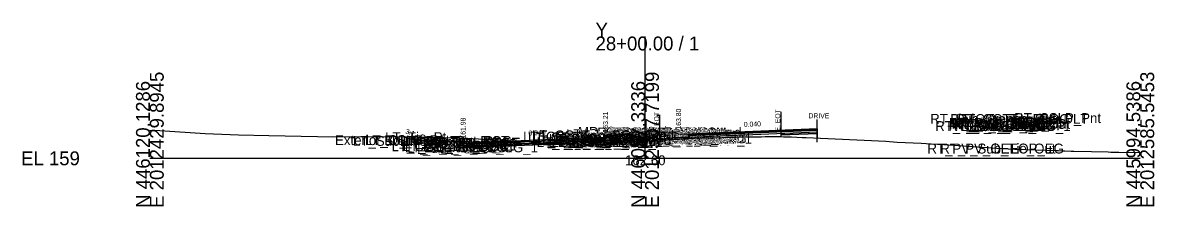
# Model space of a CAD drawing. Extents: x -26 to 3203, y -10 to 9532.
# Drawn here: x 1974.3 to 2202.8, y 1990.3 to 2027.4 of the extents above; entities that cross this region are included whole.
import ezdxf

# ---------------------------------------------------------------- set-up
doc = ezdxf.new("R2010")
doc.units = 0
for name, color, linetype in [('Default', 7, 'Continuous'), ('Exist CMT Pavement', 7, 'Continuous'), ('Exist Cross Section Cell', 7, 'Continuous'), ('Exist XS Center Line Elevation Label', 7, 'Continuous'), ('Exist XS Ground Line', 7, 'Continuous'), ('Prop CMT Conc Surface', 7, 'Continuous'), ('Prop CMT Concrete Structures', 7, 'Continuous'), ('Prop CMT Pvmt Course 1', 7, 'Continuous'), ('Prop CMT Pvmt Course 1 CG', 7, 'Continuous'), ('Prop CMT Pvmt Course 2', 7, 'Continuous'), ('Prop CMT Pvmt Course 2 Wedge', 7, 'Continuous'), ('Prop CMT Pvmt Course 3', 7, 'Continuous'), ('Prop CMT Pvmt Course 3 Wedge', 7, 'Continuous'), ('Prop CMT Pvmt Surface', 7, 'Continuous'), ('Prop CMT Shear Line', 7, 'Continuous'), ('Prop CMT Shear Line Text', 7, 'Continuous'), ('Prop CMT Slope Grass', 7, 'Continuous'), ('Prop CMT Subgrade Earthwork', 7, 'Continuous'), ('Prop XS Hydro Elevations', 7, 'Continuous'), ('Prop XS Label Text', 7, 'Continuous'), ('Prop XS SE Text', 7, 'Continuous'), ('Prop XS Side Slope Text', 7, 'Continuous'), ('Scratch_Level_0', 7, 'Continuous')]:
    doc.layers.add(name, color=color, linetype=linetype)

msp = doc.modelspace()

# ---------------------------------------------------------------- linework, layer by layer
at = {"layer": 'Exist CMT Pavement'}
msp.add_lwpolyline([(2102.94, 2003.8), (2103.42, 2003.84), (2104, 2003.86), (2105.57, 2003.91), (2106.47, 2003.95), (2107.66, 2004), (2108.25, 2004.02), (2108.72, 2004.03), (2111.56, 2004.1), (2111.97, 2004.11), (2113.68, 2004.16), (2115.52, 2004.23), (2116.81, 2004.25), (2118.35, 2004.29), (2119.47, 2004.31), (2120.62, 2004.34), (2121.54, 2004.35), (2122.41, 2004.35), (2123.51, 2004.36), (2124.23, 2004.37), (2124.81, 2004.38), (2126.83, 2004.38), (2127.38, 2004.37), (2127.38, 2004.37)], dxfattribs=at)
at = {"layer": 'Exist Cross Section Cell'}
for p, q in [((2100, 2000), (2100, 2024.57)), ((2000, 2000), (2100, 2000)), ((2100, 2000), (2200, 2000))]:
    msp.add_line(p, q, dxfattribs=at)
at = {"layer": 'Exist XS Ground Line'}
msp.add_lwpolyline([(2000, 2005.67), (2001.98, 2005.58), (2011.14, 2004.99), (2017.91, 2004.74), (2023.99, 2004.6), (2033.83, 2004.38), (2036.84, 2004.34), (2049.76, 2004.39), (2062.54, 2004.11), (2063.94, 2004.04), (2073.65, 2003.51), (2076.49, 2003.36), (2076.94, 2003.34), (2077.71, 2003.28), (2088.98, 2002.56), (2093.02, 2003.01), (2095.39, 2003.3), (2100, 2003.6), (2102.94, 2003.8), (2103.42, 2003.84), (2104, 2003.86), (2105.57, 2003.91), (2106.47, 2003.95), (2107.66, 2004), (2108.25, 2004.02), (2108.72, 2004.03), (2111.56, 2004.1), (2111.97, 2004.11), (2113.68, 2004.16), (2115.52, 2004.23), (2116.81, 2004.25), (2118.35, 2004.29), (2119.47, 2004.31), (2120.62, 2004.34), (2121.54, 2004.35), (2122.41, 2004.35), (2123.51, 2004.36), (2124.23, 2004.37), (2124.81, 2004.38), (2126.83, 2004.38), (2127.38, 2004.37), (2127.96, 2004.35), (2129.55, 2004.32), (2131.7, 2004.23), (2132.54, 2004.2), (2148.62, 2003.47), (2150.91, 2003.29), (2155.77, 2003.06), (2157.8, 2002.94), (2160.31, 2002.8), (2171.98, 2001.98), (2174.64, 2001.83), (2183.16, 2001.58), (2183.47, 2001.58), (2184.15, 2001.54), (2184.79, 2001.5), (2186.07, 2001.46), (2186.61, 2001.45), (2190.16, 2001.36), (2193.53, 2001.28), (2194.02, 2001.27), (2194.59, 2001.26), (2195.65, 2001.22), (2200, 2001.15)], dxfattribs=at)
at = {"layer": 'Prop CMT Conc Surface'}
for points in [[(2091.25, 2004.18), (2092, 2004.21), (2092, 2004.37), (2092.76, 2004.62)], [(2108.75, 2004.88), (2106.75, 2004.8), (2106.75, 2004.96), (2106, 2005.21)], [(2058.75, 2003.57), (2053.75, 2003.67)], [(2063.25, 2002.98), (2063.25, 2003.48), (2062.75, 2003.48)], [(2065.25, 2003.14), (2063.25, 2002.98)]]:
    msp.add_lwpolyline(points, dxfattribs=at)
at = {"layer": 'Prop CMT Concrete Structures'}
for points in [[(2091.25, 2004.18), (2092, 2004.21), (2092, 2004.37), (2092.76, 2004.62)], [(2092.76, 2004.62), (2092.76, 2003.65)], [(2108.75, 2004.88), (2106.75, 2004.8), (2106.75, 2004.96), (2106, 2005.21)], [(2106, 2005.21), (2106, 2004.18)], [(2106, 2004.18), (2108.75, 2004.29)], [(2108.75, 2004.29), (2108.75, 2004.88)], [(2053.75, 2003.33), (2053.75, 2003.67)], [(2053.75, 2003.67), (2058.75, 2003.57)], [(2058.75, 2003.23), (2053.75, 2003.33)], [(2058.75, 2003.57), (2058.75, 2003.23)], [(2065.25, 2003.14), (2063.25, 2002.98), (2063.25, 2003.48), (2062.75, 2003.48)], [(2062.75, 2003.48), (2062.75, 2002.45), (2065.25, 2002.55)], [(2065.25, 2002.55), (2065.25, 2003.14)], [(2091.25, 2003.59), (2091.25, 2004.18)], [(2092.76, 2003.65), (2091.25, 2003.59)]]:
    msp.add_lwpolyline(points, dxfattribs=at)
at = {"layer": 'Prop CMT Pvmt Course 1'}
for points in [[(2172.41, 2007.42), (2172.41, 2007.17)], [(2108.75, 2004.88), (2134.75, 2005.92)], [(2134.75, 2005.67), (2108.75, 2004.63)], [(2108.75, 2004.63), (2108.75, 2004.88)], [(2108.75, 2004.63), (2108.75, 2004.63)], [(2134.75, 2005.92), (2134.75, 2005.67)], [(2134.75, 2005.92), (2134.75, 2005.67)], [(2091.25, 2004.18), (2065.25, 2003.14)], [(2065.25, 2002.89), (2091.25, 2003.93)], [(2065.25, 2003.14), (2065.25, 2002.89)], [(2091.25, 2003.93), (2091.25, 2004.18)], [(2091.25, 2003.93), (2091.25, 2003.93), (2091.25, 2003.93)]]:
    msp.add_lwpolyline(points, dxfattribs=at)
at = {"layer": 'Prop CMT Pvmt Course 1 CG'}
for points in [[(2108.75, 2004.29), (2105.5, 2004.16), (2105.15, 2003.82)], [(2108.75, 2003.96), (2108.75, 2004.29)], [(2134.75, 2005), (2134.75, 2005.33)], [(2065.25, 2002.55), (2062.25, 2002.43), (2061.9, 2002.09)], [(2061.9, 2002.09), (2065.25, 2002.22)], [(2065.25, 2002.22), (2065.25, 2002.55)], [(2091.25, 2003.59), (2093.26, 2003.67), (2093.58, 2003.35)], [(2091.25, 2003.26), (2091.25, 2003.59)], [(2093.58, 2003.35), (2091.25, 2003.26)], [(2105.15, 2003.82), (2108.75, 2003.96)]]:
    msp.add_lwpolyline(points, dxfattribs=at)
at = {"layer": 'Prop CMT Pvmt Course 2'}
msp.add_lwpolyline([(2108.75, 2004.63), (2108.75, 2004.29), (2108.75, 2004.29)], close=True, dxfattribs=at)
for points in [[(2108.75, 2004.63), (2108.75, 2004.63)], [(2134.75, 2005.67), (2134.75, 2005.33)], [(2091.25, 2003.93), (2065.25, 2002.89)], [(2065.25, 2002.55), (2091.25, 2003.59)], [(2065.25, 2002.89), (2065.25, 2002.55)], [(2091.25, 2003.59), (2091.25, 2003.93)]]:
    msp.add_lwpolyline(points, dxfattribs=at)
at = {"layer": 'Prop CMT Pvmt Course 2 Wedge'}
msp.add_lwpolyline([(2108.75, 2004.63), (2134.75, 2005.67)], dxfattribs=at)
at = {"layer": 'Prop CMT Pvmt Course 3'}
for points in [[(2108.75, 2004.29), (2108.75, 2004.29), (2108.75, 2003.96), (2108.75, 2003.96)], [(2108.75, 2003.96), (2108.75, 2004.29)], [(2127.38, 2004.71), (2134.75, 2005)], [(2134.75, 2005.33), (2134.75, 2004.22)], [(2091.25, 2003.59), (2065.25, 2002.55)], [(2065.25, 2002.22), (2091.25, 2003.26)], [(2065.25, 2002.55), (2065.25, 2002.22)], [(2091.25, 2003.26), (2091.25, 2003.59)]]:
    msp.add_lwpolyline(points, dxfattribs=at)
at = {"layer": 'Prop CMT Pvmt Course 3 Wedge'}
msp.add_lwpolyline([(2108.75, 2004.29), (2134.75, 2005.33)], dxfattribs=at)
at = {"layer": 'Prop CMT Pvmt Surface'}
for points in [[(2134.75, 2005.92), (2108.75, 2004.88)], [(2091.25, 2004.18), (2065.25, 2003.14)]]:
    msp.add_lwpolyline(points, dxfattribs=at)
at = {"layer": 'Prop CMT Shear Line'}
msp.add_line((2134.75, 2003.28), (2134.75, 2007.86), dxfattribs=at)
at = {"layer": 'Prop CMT Slope Grass'}
for points in [[(2053.25, 2003.67), (2051.17, 2004.36)], [(2092.76, 2004.62), (2099.38, 2005.35)], [(2106, 2005.21), (2099.38, 2005.35)], [(2062.75, 2003.48), (2053.25, 2003.67)]]:
    msp.add_lwpolyline(points, dxfattribs=at)
at = {"layer": 'Prop CMT Subgrade Earthwork'}
for points in [[(2095.11, 2004.88), (2093.58, 2003.35)], [(2103.71, 2005.26), (2105.15, 2003.82)], [(2134.75, 2005), (2127.38, 2004.71)], [(2134.75, 2005.33), (2134.75, 2004.1)], [(2134.75, 2005), (2134.75, 2005)], [(2065.25, 2002.22), (2061.9, 2002.09), (2060.47, 2003.52)], [(2091.25, 2003.26), (2065.25, 2002.22)], [(2065.25, 2002.22), (2065.25, 2002.22)], [(2093.58, 2003.35), (2091.25, 2003.26)], [(2091.25, 2003.26), (2091.25, 2003.26)], [(2091.25, 2003.26), (2091.25, 2003.26)], [(2105.15, 2003.82), (2108.75, 2003.96)], [(2108.75, 2003.96), (2108.74, 2004.03)], [(2108.75, 2003.96), (2108.75, 2003.96)], [(2108.75, 2003.96), (2108.75, 2003.96)]]:
    msp.add_lwpolyline(points, dxfattribs=at)
at = {"layer": 'Prop XS Label Text'}
for p, q in [((2127.38, 2009.37), (2127.38, 2004.37)), ((2102.94, 2008.8), (2102.94, 2003.8))]:
    msp.add_line(p, q, dxfattribs=at)

# ---------------------------------------------------------------- texts
at = {"layer": 'Default'}
msp.add_text('-', height=0.0001, dxfattribs=at).set_placement((2000, 2000))
at = {"layer": 'Exist Cross Section Cell'}
for s, p in [('Y', (2090, 2024.57)), ('28+00.00 / 1', (2090, 2021.77)), ('EL 159', (1974, 1998.6))]:
    msp.add_text(s, height=2.8, dxfattribs=at).set_placement(p)
for s, p in [('E 2012429.8945', (2002.8, 1990)), ('E 2012507.7199', (2102.8, 1990)), ('E 2012585.5453', (2202.8, 1990)), ('N 446120.1286', (2000, 1990)), ('N 446057.3336', (2100, 1990)), ('N 445994.5386', (2200, 1990))]:
    msp.add_text(s, height=2.8, rotation=90, dxfattribs=at).set_placement(p)
at = {"layer": 'Exist XS Center Line Elevation Label'}
msp.add_text('162.60', height=2, dxfattribs=at).set_placement((2095.95, 1998.6))
at = {"layer": 'Prop CMT Shear Line Text'}
msp.add_text('DRIVE', height=1, rotation=360, dxfattribs=at).set_placement((2132.99, 2008.08))
at = {"layer": 'Prop XS Hydro Elevations'}
for s, p in [('163.21', (2092.5, 2005.21)), ('163.80', (2107.25, 2005.8)), ('161.98', (2063.75, 2003.98))]:
    msp.add_text(s, height=1, rotation=90, dxfattribs=at).set_placement(p)
at = {"layer": 'Prop XS Label Text'}
for p in [(2102.84, 2004.82), (2127.28, 2005.4)]:
    msp.add_text('E. EOT', height=1, rotation=90, dxfattribs=at).set_placement(p)
at = {"layer": 'Prop XS SE Text'}
for p in [(2119.96, 2006.33), (2076.46, 2004.59)]:
    msp.add_text('0.040', height=1, rotation=2.2906, dxfattribs=at).set_placement(p)
at = {"layer": 'Prop XS Side Slope Text'}
msp.add_text('3:1', height=1, rotation=341.5651, dxfattribs=at).set_placement((2051.51, 2005.04))
at = {"layer": 'Scratch_Level_0'}
for s, p in [('RT_Sub_Trench_Out_DLT', (2157.57, 2006.97)), ('RT_CG_Top_Face', (2161.62, 2006.92)), ('RT_CG_Top_BOC', (2163.14, 2006.92)), ('RT_CSLP_Pnt', (2174.53, 2007.11)), ('RT_Sub_OEOT_CG_1', (2158.58, 2005.51)), ('RT_Sub_OEEOP', (2161.27, 2005.49)), ('RT_PV2_OEEOP', (2161.36, 2006.16)), ('RT_PV3_OEEOP', (2161.36, 2005.83)), ('RT_CG1_Shelf_Out', (2161.91, 2005.96)), ('RT_CG_Bot_IE', (2162.27, 2005.84)), ('RT_Sub_OEOT', (2162.44, 2005.51)), ('RT_PV2_OEOT', (2162.53, 2006.17)), ('RT_PV3_OEOT', (2162.53, 2005.84)), ('RT_CG_Top_Gut', (2162.6, 2006.42)), ('RT_PV1_OEOT', (2163.1, 2006.42)), ('RT_CG_Bot_BOC', (2163.17, 2005.94)), ('RT_Sub_OEOP', (2165.79, 2005.64)), ('Exterior Boundary', (2037.39, 2002.67)), ('LT_Sub_Trench_Out_DLT', (2041.03, 2002.52)), ('LT_CSLP_Pnt', (2043.42, 2002.67)), ('LT_Tie_Pt', (2047.51, 2003.27)), ('LT_CG_Top_Face', (2050.51, 2002.48)), ('LT_CG_Top_BOC', (2051.03, 2002.48)), ('LT_CG_Top_Face_Med', (2075.37, 2003.37)), ('LT_CG_Top_Gut_Med', (2076.35, 2003.21)), ('LT_CG_Top_BOC_Med', (2077.15, 2003.62)), ('LT_CG_Bot_BOC_Med', (2077.19, 2002.65)), ('LT_CG_Bot_IE_Med', (2077.31, 2002.59)), ('LT_Sub_IEOT_CG_1', (2078.12, 2002.26)), ('LT_Sub_OEEOP', (2080.46, 2002.26)), ('LT_PV2_OEEOP', (2080.56, 2002.93)), ('LT_PV3_OEEOP', (2080.56, 2002.59)), ('LT_Sub_IEEOP', (2081.11, 2002.26)), ('LT_PV2_IEEOP', (2081.2, 2002.93)), ('LT_CG1_Shelf_In', (2081.43, 2002.67)), ('LT_Sub_PGL', (2082.37, 2002.26)), ('LT_PV2_PGL', (2082.46, 2002.93)), ('LT_PV1_PGL', (2083.03, 2003.18)), ('LT_Sub_DLT_In', (2084.05, 2003.88)), ('LT_Sub_IEOP', (2084.34, 2002.35)), ('MD_Crown Point', (2086.45, 2004.35)), ('RT_CG_Top_BOC_Med', (2090.35, 2004.21)), ('RT_CG_Bot BOC In', (2091.84, 2003.18)), ('RT_CG_Top_BOC In', (2091.97, 2004.21)), ('RT_Sub_DLT_In', (2092.61, 2004.26)), ('RT_CG_Top FOC In', (2092.61, 2003.96)), ('RT_CG_Top_Gut In', (2092.64, 2003.8)), ('RT_CG1_Shelf_In', (2093.63, 2003.16)), ('RT_CG_Bot_IE_Med', (2094.77, 2003.29)), ('RT_PV_Sub_Tie_In', (2095.25, 2003.03)), ('RT_Sub_IEOT_CG_1', (2095.57, 2002.96)), ('RT_Sub_IEOP', (2095.86, 2002.82)), ('RT_PV_IEEOP_EG', (2096.89, 2003.03)), ('RT_Sub_IEEOP', (2098.56, 2002.96)), ('RT_PV2_IEEOP', (2098.66, 2003.63)), ('RT_PV3_IEEOP', (2098.66, 2003.29)), ('RT_Sub_PGL', (2099.82, 2002.96)), ('RT_PV2_PGL', (2099.92, 2003.63)), ('RT_PV3_PGL', (2099.92, 2003.29)), ('RT_PV1_PGL', (2100.48, 2003.88)), ('LT_CG1_Shelf_Out', (2048.8, 2001.43)), ('LT_CG_Bot_BOC', (2051.06, 2001.45)), ('LT_Sub_OEOT_CG_1', (2051.47, 2001.22)), ('LT_CG_Top_Gut', (2051.49, 2001.98)), ('LT_Sub_OEOP', (2052.01, 2001.09)), ('LT_CG_Bot_IE', (2055.16, 2001.55)), ('LT_Sub_OEOT', (2055.33, 2001.22)), ('LT_PV2_OEOT', (2055.42, 2001.89)), ('LT_PV3_OEOT', (2055.42, 2001.55)), ('LT_PV1_OEOT', (2055.99, 2002.14)), ('RT_PV_Sub_Tie_Out', (2157.01, 2000.97)), ('RT_PV_OEEOP_EG', (2159.6, 2000.97))]:
    msp.add_text(s, height=2, dxfattribs=at).set_placement(p)

doc.saveas('drawing.dxf')
